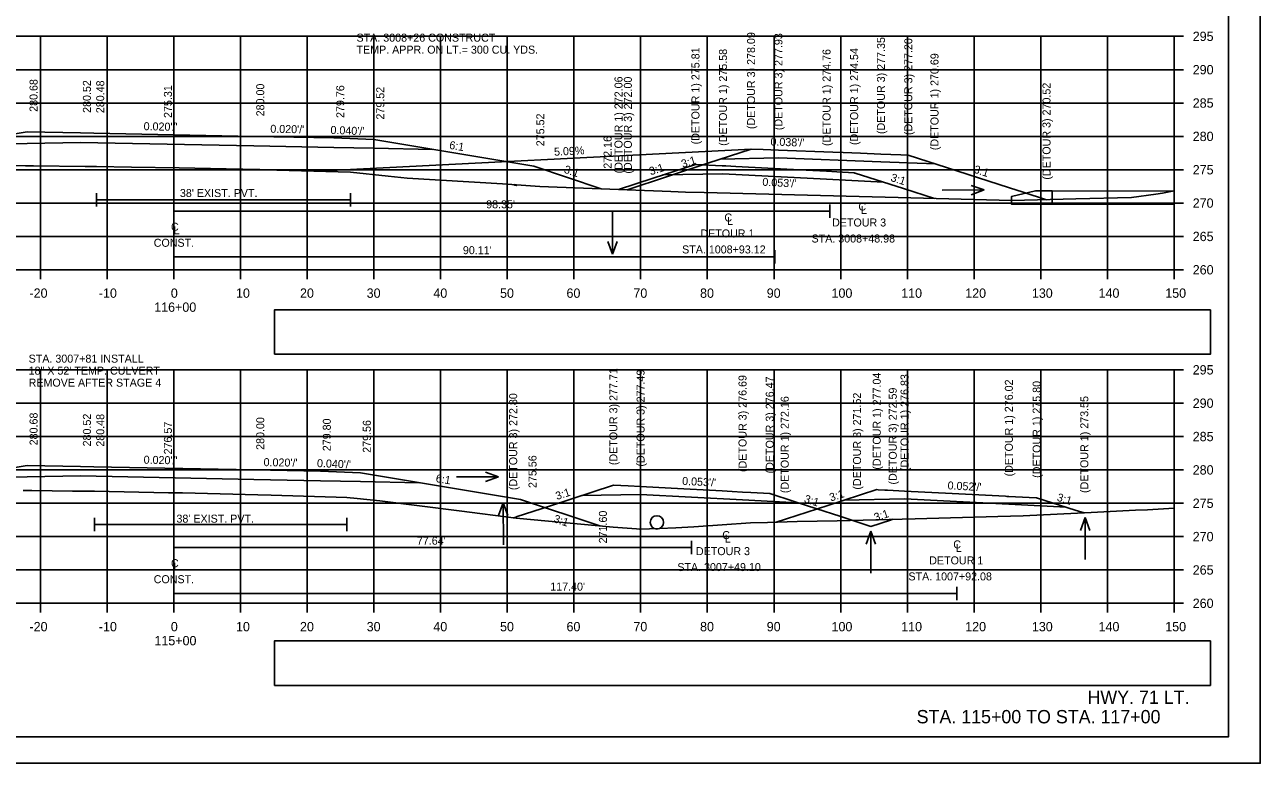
# Model space of a CAD drawing. Extents: x 285 to 4233, y -659 to 3710.
# Drawn here: x 516.9 to 702.2, y 616.2 to 726.9 of the extents above; entities that cross this region are included whole.
import ezdxf

# ---------------------------------------------------------------- set-up
doc = ezdxf.new("R2010")
doc.units = 0
for name, color, linetype in [('R_Alt Surface', 7, 'Continuous'), ('R_Axis', 7, 'Continuous'), ('R_Axis Annot', 7, 'Continuous'), ('R_Border', 7, 'Continuous'), ('R_Detour', 7, 'Continuous'), ('R_Draft', 7, 'Continuous'), ('R_Drive', 7, 'Continuous'), ('R_Exist Surface', 7, 'Continuous'), ('R_Fin Surface', 7, 'Continuous'), ('R_Grid', 7, 'Continuous'), ('R_No Plot', 7, 'Continuous'), ('R_Proposed Const Limits', 7, 'Continuous'), ('R_Water', 7, 'Continuous'), ('R_Water Annot', 7, 'Continuous'), ('R_Xsect Elev', 7, 'Continuous'), ('R_Xsect Slope', 7, 'Continuous')]:
    doc.layers.add(name, color=color, linetype=linetype)

# ---------------------------------------------------------------- blocks, each defined once
blk = doc.blocks.new('FES24LT_P')
at = {"layer": 'R_Water'}
blk.add_lwpolyline([(2.5, 0), (2.5, -2), (-3.625, -2), (-3.625, -0.875), (0, 0)], close=True, dxfattribs=at)

msp = doc.modelspace()

# ---------------------------------------------------------------- linework, layer by layer
at = {"layer": 'R_Alt Surface'}
for points in [[(505.44, 708.87), (517.28, 709.11), (525.28, 709.27), (551.28, 708.75), (563.28, 708.51), (569.28, 708.39), (578.12, 708.21)], [(527.67, 701.65), (527.67, 699.65)], [(527.67, 700.65), (565.77, 700.65)], [(565.77, 701.65), (565.77, 699.65)], [(539.28, 699.97), (539.28, 697.97)], [(539.28, 698.97), (637.63, 698.97)], [(637.63, 699.97), (637.63, 697.97)], [(539.28, 693.1), (539.28, 691.1)], [(629.39, 693.1), (629.39, 691.1)], [(539.28, 692.1), (629.39, 692.1)], [(505.44, 658.87), (517.28, 659.11), (525.28, 659.27), (551.28, 658.75), (561.26, 658.55), (567.26, 658.43), (576.1, 658.25)], [(527.36, 652.97), (527.36, 650.97)], [(565.23, 652.97), (565.23, 650.97)], [(527.36, 651.97), (565.23, 651.97)], [(539.28, 649.53), (539.28, 647.53)], [(616.92, 649.53), (616.92, 647.53)], [(539.28, 648.53), (616.92, 648.53)], [(539.28, 642.66), (539.28, 640.66)], [(539.28, 641.66), (656.68, 641.66)], [(656.68, 642.66), (656.68, 640.66)]]:
    msp.add_lwpolyline(points, dxfattribs=at)
at = {"layer": 'R_Axis'}
for p, q in [((689.28, 690.17), (689.28, 725.17)), ((690.68, 725.17), (689.28, 725.17)), ((690.68, 720.17), (689.28, 720.17)), ((690.68, 715.17), (689.28, 715.17)), ((690.68, 710.17), (689.28, 710.17)), ((690.68, 705.17), (689.28, 705.17)), ((690.68, 700.17), (689.28, 700.17)), ((690.68, 695.17), (689.28, 695.17)), ((389.28, 690.17), (689.28, 690.17)), ((519.28, 688.77), (519.28, 690.17)), ((529.28, 688.77), (529.28, 690.17)), ((539.28, 688.77), (539.28, 690.17)), ((549.28, 688.77), (549.28, 690.17)), ((559.28, 688.77), (559.28, 690.17)), ((569.28, 688.77), (569.28, 690.17)), ((579.28, 688.77), (579.28, 690.17)), ((589.28, 688.77), (589.28, 690.17)), ((599.28, 688.77), (599.28, 690.17)), ((609.28, 688.77), (609.28, 690.17)), ((619.28, 688.77), (619.28, 690.17)), ((629.28, 688.77), (629.28, 690.17)), ((639.28, 688.77), (639.28, 690.17)), ((649.28, 688.77), (649.28, 690.17)), ((659.28, 688.77), (659.28, 690.17)), ((669.28, 688.77), (669.28, 690.17)), ((679.28, 688.77), (679.28, 690.17)), ((689.28, 688.77), (689.28, 690.17)), ((690.68, 690.17), (689.28, 690.17)), ((689.28, 640.17), (689.28, 675.17)), ((690.68, 675.17), (689.28, 675.17)), ((690.68, 670.17), (689.28, 670.17)), ((690.68, 665.17), (689.28, 665.17)), ((690.68, 660.17), (689.28, 660.17)), ((690.68, 655.17), (689.28, 655.17)), ((690.68, 650.17), (689.28, 650.17)), ((690.68, 645.17), (689.28, 645.17)), ((389.28, 640.17), (689.28, 640.17)), ((519.28, 638.77), (519.28, 640.17)), ((529.28, 638.77), (529.28, 640.17)), ((539.28, 638.77), (539.28, 640.17)), ((549.28, 638.77), (549.28, 640.17)), ((559.28, 638.77), (559.28, 640.17)), ((569.28, 638.77), (569.28, 640.17)), ((579.28, 638.77), (579.28, 640.17)), ((589.28, 638.77), (589.28, 640.17)), ((599.28, 638.77), (599.28, 640.17)), ((609.28, 638.77), (609.28, 640.17)), ((619.28, 638.77), (619.28, 640.17)), ((629.28, 638.77), (629.28, 640.17)), ((639.28, 638.77), (639.28, 640.17)), ((649.28, 638.77), (649.28, 640.17)), ((659.28, 638.77), (659.28, 640.17)), ((669.28, 638.77), (669.28, 640.17)), ((679.28, 638.77), (679.28, 640.17)), ((689.28, 638.77), (689.28, 640.17)), ((690.68, 640.17), (689.28, 640.17))]:
    msp.add_line(p, q, dxfattribs=at)
at = {"layer": 'R_Axis Annot'}
for points in [[(554.36, 677.5), (694.72, 677.5), (694.72, 684.15), (554.36, 684.15)], [(554.36, 627.86), (694.72, 627.86), (694.72, 634.52), (554.36, 634.52)]]:
    msp.add_lwpolyline(points, close=True, dxfattribs=at)
at = {"layer": 'R_Border'}
for q in [(697.46, 825.63), (381.28, 620.17)]:
    msp.add_line((697.46, 620.17), q, dxfattribs=at)
at = {"layer": 'R_Detour'}
for points in [[(607.24, 702.17), (619.38, 706.14), (625.84, 708.26), (627.64, 708.19), (629.94, 708.1), (638.12, 707.79), (639.65, 707.73), (642.24, 707.63), (645.32, 707.52), (648.32, 707.4), (649.42, 707.36), (656.69, 705.02), (664.59, 702.48), (666.67, 701.81), (670.15, 700.68)], [(621.22, 706.74), (629.94, 706.93), (645.32, 706.35), (653.51, 706.05)], [(605.96, 702.22), (611.15, 703.91), (617.5, 705.97), (621.52, 705.76), (621.63, 705.75), (622.07, 705.73), (623.56, 705.65), (634.1, 705.09), (635.09, 705.04), (637.16, 704.93), (638.71, 704.84), (641.3, 704.71), (641.4, 704.67), (641.47, 704.65), (648.71, 702.34), (653.35, 700.86)], [(612.62, 704.39), (621.63, 704.58), (637.16, 703.76), (645.68, 703.31)], [(590.16, 652.97), (590.57, 653.1), (590.78, 653.17), (595.59, 654.74), (605.19, 657.88), (607.42, 657.76), (609.27, 657.66), (613.85, 657.42), (621.5, 657.01), (622.99, 656.94), (624.56, 656.85), (625.78, 656.79), (628.64, 656.64), (632.3, 655.44), (635.72, 654.33), (639.13, 653.22), (643.8, 651.69), (646.74, 652.64), (647.09, 652.76)], [(600.43, 656.32), (609.27, 656.49), (624.56, 655.69), (632.89, 655.25)], [(629.6, 652.33), (637.34, 654.83), (644.69, 657.21), (644.92, 657.2), (645.88, 657.15), (646.15, 657.13), (646.29, 657.13), (648.86, 656.99), (655.99, 656.63), (664, 656.21), (664.22, 656.2), (664.5, 656.19), (667.53, 656.03), (668.67, 655.97), (674.47, 654.14), (675.82, 653.71)], [(639.78, 655.62), (648.86, 655.83), (664.5, 655.02), (673.09, 654.57)]]:
    msp.add_lwpolyline(points, dxfattribs=at)
at = {"layer": 'R_Drive'}
msp.add_line((560.82, 704.95), (625.84, 708.26), dxfattribs=at)
at = {"layer": 'R_Exist Surface'}
for points in [[(512.65, 705.79), (517.01, 705.77), (518.23, 705.77), (525.98, 705.67), (527.67, 705.65), (532.92, 705.57), (540.08, 705.46), (547.13, 705.29), (552.16, 705.18), (554.72, 705.11), (565.77, 704.82), (571.41, 704.21), (574.28, 703.9), (588.57, 703.05), (594.18, 702.68), (613.82, 701.92), (616.03, 701.83), (618.81, 701.75), (643.98, 701.09), (647.88, 701.01), (664.96, 700.54), (674.56, 700.8), (682.89, 701.03), (686.54, 701.5), (687.57, 701.68), (689.28, 702.02)], [(516.65, 657.08), (517.95, 657.06), (524.06, 657), (527.36, 656.97), (538.48, 656.75), (539.51, 656.73), (540.59, 656.71), (551.86, 656.44), (553.88, 656.38), (565.23, 656.04), (566.75, 655.89), (570.15, 655.51), (582.04, 654.04), (590.61, 652.91), (605.14, 651.59), (608.67, 651.31), (609.1, 651.28), (612.09, 651.38), (614.56, 651.47), (617.27, 651.65), (625.75, 652.22), (628.28, 652.29), (632.76, 652.42), (638.75, 652.55), (650.46, 652.84), (662.84, 653.18), (666.67, 653.29), (676.84, 653.76), (683.51, 654.11), (685.28, 654.2), (689.28, 654.45)]]:
    msp.add_lwpolyline(points, dxfattribs=at)
at = {"layer": 'R_Fin Surface'}
for points in [[(476.06, 702.73), (479.49, 701.58), (497.28, 707.51), (517.28, 710.85), (525.28, 710.69), (527.28, 710.65), (551.28, 710.17), (563.28, 709.93), (569.28, 709.69), (593.28, 705.69), (603.37, 702.32)], [(478.14, 652.78), (480.6, 651.95), (497.28, 657.51), (517.28, 660.85), (525.28, 660.69), (527.28, 660.65), (551.28, 660.17), (561.26, 659.97), (567.26, 659.73), (591.26, 655.73), (603.14, 651.77)]]:
    msp.add_lwpolyline(points, dxfattribs=at)
at = {"layer": 'R_Grid'}
for p, q in [((389.28, 725.17), (689.28, 725.17)), ((519.28, 690.17), (519.28, 725.17)), ((529.28, 690.17), (529.28, 725.17)), ((539.28, 690.17), (539.28, 725.17)), ((549.28, 690.17), (549.28, 725.17)), ((559.28, 690.17), (559.28, 725.17)), ((569.28, 690.17), (569.28, 725.17)), ((579.28, 690.17), (579.28, 725.17)), ((589.28, 690.17), (589.28, 725.17)), ((599.28, 690.17), (599.28, 725.17)), ((609.28, 690.17), (609.28, 725.17)), ((619.28, 690.17), (619.28, 725.17)), ((629.28, 690.17), (629.28, 725.17)), ((639.28, 690.17), (639.28, 725.17)), ((649.28, 690.17), (649.28, 725.17)), ((659.28, 690.17), (659.28, 725.17)), ((669.28, 690.17), (669.28, 725.17)), ((679.28, 690.17), (679.28, 725.17)), ((689.28, 690.17), (689.28, 725.17)), ((389.28, 720.17), (689.28, 720.17)), ((389.28, 715.17), (689.28, 715.17)), ((389.28, 710.17), (689.28, 710.17)), ((389.28, 705.17), (689.28, 705.17)), ((389.28, 700.17), (689.28, 700.17)), ((389.28, 695.17), (689.28, 695.17)), ((389.28, 690.17), (689.28, 690.17)), ((389.28, 675.17), (689.28, 675.17)), ((519.28, 640.17), (519.28, 675.17)), ((529.28, 640.17), (529.28, 675.17)), ((539.28, 640.17), (539.28, 675.17)), ((549.28, 640.17), (549.28, 675.17)), ((559.28, 640.17), (559.28, 675.17)), ((569.28, 640.17), (569.28, 675.17)), ((579.28, 640.17), (579.28, 675.17)), ((589.28, 640.17), (589.28, 675.17)), ((599.28, 640.17), (599.28, 675.17)), ((609.28, 640.17), (609.28, 675.17)), ((619.28, 640.17), (619.28, 675.17)), ((629.28, 640.17), (629.28, 675.17)), ((639.28, 640.17), (639.28, 675.17)), ((649.28, 640.17), (649.28, 675.17)), ((659.28, 640.17), (659.28, 675.17)), ((669.28, 640.17), (669.28, 675.17)), ((679.28, 640.17), (679.28, 675.17)), ((689.28, 640.17), (689.28, 675.17)), ((389.28, 670.17), (689.28, 670.17)), ((389.28, 665.17), (689.28, 665.17)), ((389.28, 660.17), (689.28, 660.17)), ((389.28, 655.17), (689.28, 655.17)), ((389.28, 650.17), (689.28, 650.17)), ((389.28, 645.17), (689.28, 645.17)), ((389.28, 640.17), (689.28, 640.17))]:
    msp.add_line(p, q, dxfattribs=at)
at = {"layer": 'R_No Plot'}
msp.add_line((368.88, 616.19), (702.21, 616.19), dxfattribs=at)
for points in [[(368.87, 829.52), (702.21, 829.52), (702.21, 616.18), (368.87, 616.18)], [(615.2, 825.63), (634.82, 825.63), (634.82, 815.75), (650.93, 815.75), (674.13, 815.75), (674.25, 787.59), (697.46, 787.59), (697.46, 620.17), (381.28, 620.17), (381.28, 825.63)]]:
    msp.add_lwpolyline(points, close=True, dxfattribs=at)
at = {"layer": 'R_Proposed Const Limits'}
for points in [[(527.28, 710.65), (527.28, 710.65), (527.28, 710.65)], [(590.3, 702.92), (590.27, 702.93), (590.26, 702.93), (590.25, 702.94), (590.42, 702.88), (590.66, 702.8), (590.69, 702.79)], [(527.28, 660.65), (527.28, 660.65), (527.28, 660.65)], [(551.28, 660.17), (551.28, 660.17), (551.28, 660.17)]]:
    msp.add_lwpolyline(points, dxfattribs=at)
msp.add_lwpolyline([(551.28, 710.17), (551.28, 710.17), (551.28, 710.17)], close=True, dxfattribs=at)
at = {"layer": 'R_Water'}
for p, q in [((671.01, 702.01), (689.28, 701.98)), ((671.01, 700.01), (689.28, 699.98))]:
    msp.add_line(p, q, dxfattribs=at)
msp.add_circle((611.72, 652.3), 1, dxfattribs=at)
at = {"layer": 'R_Water Annot'}
for p, q in [((660.78, 702.14), (658.86, 702.83)), ((654.5, 702.12), (660.78, 702.14)), ((660.78, 702.14), (658.86, 701.43)), ((605.06, 698.79), (605.08, 692.5)), ((605.08, 692.5), (604.37, 694.42)), ((605.08, 692.5), (605.77, 694.43)), ((587.95, 659.13), (586.03, 659.83)), ((581.67, 659.13), (587.95, 659.13)), ((587.95, 659.13), (586.03, 658.43)), ((588.67, 655.23), (587.98, 653.31)), ((588.69, 648.95), (588.67, 655.23)), ((588.67, 655.23), (589.38, 653.31)), ((675.95, 653.02), (675.26, 651.1)), ((675.97, 646.74), (675.95, 653.02)), ((675.95, 653.02), (676.66, 651.1)), ((643.78, 650.96), (643.08, 649.04)), ((643.8, 644.68), (643.78, 650.96)), ((643.78, 650.96), (644.48, 649.04))]:
    msp.add_line(p, q, dxfattribs=at)
at = {"layer": 'R_Xsect Elev'}
for p, q in [((539.28, 705.47), (539.28, 718.13)), ((539.28, 656.74), (539.28, 668.34))]:
    msp.add_line(p, q, dxfattribs=at)

# ---------------------------------------------------------------- block references
at = {"layer": 'R_Water', "rotation": -0.10462589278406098}
msp.add_blockref('FES24LT_P', (668.51, 702.02), dxfattribs=at)

# ---------------------------------------------------------------- texts
at = {"layer": 'R_Alt Surface'}
for s, height, p in [('C', 1.2, (621.84, 697.41)), ('C', 1.2, (641.94, 699.06)), ('L', 1.2, (642.32, 698.53)), ('C', 1.2, (538.84, 696.02)), ('L', 1.2, (622.23, 696.88)), ('DETOUR 3', 1.199, (637.99, 696.66)), ('L', 1.2, (539.23, 695.49)), ('DETOUR 1', 1.199, (618.24, 695.02)), ('STA. 3008+48.98', 1.1985, (634.91, 694.26)), ('CONST.', 1.199, (536.25, 693.62)), ('STA. 1008+93.12', 1.1985, (615.5, 692.62)), ('C', 1.2, (621.52, 649.79)), ('L', 1.2, (621.9, 649.26)), ('DETOUR 3', 1.199, (617.57, 647.39)), ('C', 1.2, (656.17, 648.4)), ('L', 1.2, (656.56, 647.87)), ('C', 1.2, (538.84, 645.58)), ('DETOUR 1', 1.199, (652.56, 646)), ('L', 1.2, (539.23, 645.05)), ('STA. 3007+49.10', 1.1985, (614.78, 645)), ('CONST.', 1.199, (536.25, 643.18)), ('STA. 1007+92.08', 1.1985, (649.44, 643.6))]:
    msp.add_text(s, height=height, dxfattribs=at).set_placement(p)
at = {"layer": 'R_Axis Annot'}
for s, p in [('295', (692.08, 724.47)), ('290', (692.08, 719.47)), ('285', (692.08, 714.47)), ('280', (692.08, 709.47)), ('275', (692.08, 704.47)), ('270', (692.08, 699.47)), ('265', (692.08, 694.47)), ('260', (692.08, 689.47)), ('-20', (517.62, 685.97)), ('-10', (528.02, 685.97)), ('0', (538.82, 685.97)), ('10', (548.59, 685.97)), ('20', (558.19, 685.97)), ('30', (568.19, 685.97)), ('40', (578.19, 685.97)), ('50', (588.19, 685.97)), ('60', (598.16, 685.97)), ('70', (608.19, 685.97)), ('80', (618.19, 685.97)), ('90', (628.19, 685.97)), ('100', (637.91, 685.97)), ('110', (648.36, 685.97)), ('120', (657.96, 685.97)), ('130', (667.96, 685.97)), ('140', (677.96, 685.97)), ('150', (687.96, 685.97)), ('116+00', (536.33, 683.87)), ('295', (692.08, 674.47)), ('290', (692.08, 669.47)), ('285', (692.08, 664.47)), ('280', (692.08, 659.47)), ('275', (692.08, 654.47)), ('270', (692.08, 649.47)), ('265', (692.08, 644.47)), ('260', (692.08, 639.47)), ('-20', (517.62, 635.97)), ('-10', (528.02, 635.97)), ('0', (538.82, 635.97)), ('10', (548.59, 635.97)), ('20', (558.19, 635.97)), ('30', (568.19, 635.97)), ('40', (578.19, 635.97)), ('50', (588.19, 635.97)), ('60', (598.16, 635.97)), ('70', (608.19, 635.97)), ('80', (618.19, 635.97)), ('90', (628.19, 635.97)), ('100', (637.91, 635.97)), ('110', (648.36, 635.97)), ('120', (657.96, 635.97)), ('130', (667.96, 635.97)), ('140', (677.96, 635.97)), ('150', (687.96, 635.97)), ('115+00', (536.36, 633.87))]:
    msp.add_text(s, height=1.4, dxfattribs=at).set_placement(p)
at = {"layer": 'R_Draft'}
for s, p in [('HWY. 71 LT.', (676.29, 625.08)), ('STA. 115+00 TO STA. 117+00', (650.67, 622.17))]:
    msp.add_text(s, height=2, dxfattribs=at).set_placement(p)
at = {"layer": 'R_Water'}
for s, p in [("38' EXIST. PVT.", (540.18, 701.08)), ("98.35'", (586.11, 699.39)), ("90.11'", (582.62, 692.51)), ("38' EXIST. PVT.", (539.66, 652.26)), ("77.64'", (575.72, 648.95)), ("117.40'", (595.72, 642.07))]:
    msp.add_text(s, height=1.2, dxfattribs=at).set_placement(p)
at = {"layer": 'R_Water Annot'}
for s, p in [('STA. 3008+26 CONSTRUCT', (566.66, 724.37)), ('TEMP. APPR. ON LT.= 300 CU. YDS.', (566.66, 722.57)), ('STA. 3007+81 INSTALL ', (517.49, 676.25)), ('18" X 52\' TEMP. CULVERT', (517.49, 674.45)), ('REMOVE AFTER STAGE 4', (517.49, 672.65))]:
    msp.add_text(s, height=1.2, dxfattribs=at).set_placement(p)
at = {"layer": 'R_Xsect Elev'}
for s, p in [('(DETOUR 3) 278.09', (626.44, 711.26)), ('(DETOUR 3) 277.93', (630.54, 711.1)), ('(DETOUR 3) 277.35', (645.92, 710.52)), ('(DETOUR 3) 277.20', (650.02, 710.36)), ('(DETOUR 1) 275.81', (618.1, 708.97)), ('(DETOUR 1) 275.58', (622.23, 708.75)), ('(DETOUR 1) 274.76', (637.76, 708.73)), ('(DETOUR 1) 274.54', (641.9, 708.87)), ('(DETOUR 1) 270.69', (653.95, 708.1)), ('(DETOUR 1) 272.06', (606.56, 704.62)), ('(DETOUR 3) 272.00', (607.96, 704.59)), ('280.68', (518.83, 713.85)), ('280.52', (526.83, 713.69)), ('280.48', (528.83, 713.65)), ('275.31', (538.98, 712.93)), ('280.00', (552.83, 713.17)), ('279.76', (564.83, 712.93)), ('279.52', (570.83, 712.69)), ('(DETOUR 3) 270.52', (670.75, 703.68)), ('275.52', (594.83, 708.69)), ('272.16', (604.92, 705.32)), ('(DETOUR 3) 277.71', (605.79, 660.88)), ('(DETOUR 3) 277.49', (609.87, 660.66)), ('(DETOUR 1) 277.04', (645.29, 660.21)), ('(DETOUR 3) 276.69', (625.16, 659.85)), ('(DETOUR 3) 276.47', (629.24, 659.64)), ('(DETOUR 1) 276.83', (649.46, 659.99)), ('(DETOUR 1) 276.02', (665.1, 659.19)), ('(DETOUR 1) 275.80', (669.27, 658.97)), ('(DETOUR 3) 272.80', (590.76, 657.13)), ('(DETOUR 1) 272.16', (631.49, 656.68)), ('(DETOUR 3) 271.52', (642.33, 657.21)), ('(DETOUR 3) 272.59', (647.69, 657.97)), ('(DETOUR 1) 273.55', (676.42, 656.71)), ('280.68', (518.83, 663.85)), ('280.52', (526.83, 663.69)), ('280.48', (528.83, 663.65)), ('276.57', (538.98, 662.49)), ('280.00', (552.83, 663.17)), ('279.80', (562.81, 662.97)), ('279.56', (568.81, 662.73)), ('275.56', (593.66, 657.45)), ('271.60', (604.22, 649.15))]:
    msp.add_text(s, height=1.2, rotation=90, dxfattribs=at).set_placement(p)
at = {"layer": 'R_Xsect Slope'}
for s, rotation, p in [("0.020'/'", 358.8542, (534.73, 711.1)), ("0.020'/'", 358.8542, (553.73, 710.72)), ("0.040'/'", 357.7094, (562.74, 710.55)), ("0.038'/'", 357.8378, (628.73, 708.81)), ('6:1', 350.5377, (580.51, 708.32)), ('5.09%', 2.9186, (596.32, 707.26)), ('3:1', 18.0085, (610.78, 704.32)), ('3:1', 18.1182, (615.59, 705.43)), ('3:1', 341.5651, (597.69, 704.74)), ('3:1', 342.3104, (646.68, 703.51)), ('3:1', 342.1434, (659.15, 704.75)), ("0.053'/'", 356.955, (627.51, 702.77)), ("0.020'/'", 358.8542, (534.73, 661.1)), ("0.020'/'", 358.8542, (552.72, 660.74)), ("0.040'/'", 357.7094, (560.72, 660.59)), ('6:1', 350.5377, (578.49, 658.36)), ("0.053'/'", 356.9843, (615.48, 657.93)), ("0.052'/'", 357.0386, (655.29, 657.26)), ('3:1', 18.0973, (596.73, 655.64)), ('3:1', 341.9238, (633.69, 655.35)), ('3:1', 17.9396, (637.81, 655.42)), ('3:1', 342.4867, (671.61, 655.57)), ('3:1', 17.9773, (644.5, 652.44)), ('3:1', 341.5651, (596.12, 652.36))]:
    msp.add_text(s, height=1.2, rotation=rotation, dxfattribs=at).set_placement(p)

doc.saveas('drawing.dxf')
